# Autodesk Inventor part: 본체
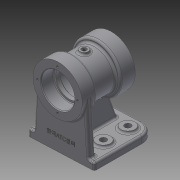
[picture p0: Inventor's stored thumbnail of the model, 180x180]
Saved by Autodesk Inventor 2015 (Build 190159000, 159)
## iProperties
Created: 2024-02
Part Number: 본체
Material: 알루미늄 6061
Document SubType Name: Modeling
Designer: 10420
Density: 2.7 g/cm^3
Appearance: 기본값
Mass: 719.296 g
Surface Area: 648.301 cm^2
Volume: 266.406 cm^3
Author: 10420
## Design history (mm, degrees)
sketch "스케치1"
  geometry: L1 (0, 0)-(0, -78); L2 (0, 0)-(35, 0); L3 (35, 0)-(35, -22); L4 (35, -22)-(28.5, -22); L5 (28.5, -22)-(28.5, -56); L6 (28.5, -56)-(35, -56); L7 (35, -56)-(35, -78); L8 (35, -78)-(0, -78)
  constraints: 16 end point, 5 perpendicular, 2 point on line, 1 horizontal, 1 vertical
  dimensions: "d0" = 78 distance of L1.start L1.end; "d1" = 70 diameter of L3 L1; "d2" = 57 diameter of L5 L1; "d3" = 22 distance between parallel lines of L2 L4; "d4" = 22 distance between parallel lines of L8 L6
revolve "회전1" sketch "스케치1" stored, may be unused: angle "d5" = 90 deg
sketch "스케치3"
  geometry: C1 r 35 at (0, 0) reference; C2 r 23.5 at (0, 0)
  constraints: 1 centre point, 1 coincident
  dimensions: "d18" = 47 diameter of C2
extrude "돌출1" cut sketch "스케치3" distance "d19" = 18; taper "d20" = 0 deg
sketch "스케치4"
  geometry: C1 r 35 at (0, 0) reference; C2 r 23.5 at (0, 0)
  constraints: 1 centre point, 1 coincident
  dimensions: "d21" = 47 diameter of C2
extrude "돌출2" cut sketch "스케치4" distance "d22" = 18; taper "d23" = 0 deg
sketch "스케치5"
  geometry: C1 r 23.5 at (0, 0) reference; C2 r 20 at (0, 0)
  constraints: 1 centre point, 1 coincident
  dimensions: "d24" = 40 diameter of C2
extrude "돌출3" cut sketch "스케치5" distance "d25" = 6; taper "d26" = 0 deg
sketch "스케치6"
  geometry: C1 r 20 at (0, 0) reference; C2 r 23.5 at (0, 0)
  constraints: 1 centre point, 1 coincident
  dimensions: "d27" = 47 diameter of C2
extrude "돌출4" cut sketch "스케치6" distance "d28" = 30; taper "d29" = 0 deg
sketch "스케치7"
  geometry: C1 r 23.5 at (0, 0) reference; C2 r 20 at (0, 0)
  constraints: 1 centre point, 1 coincident
  dimensions: "d30" = 40 diameter of C2
extrude "돌출5" cut sketch "스케치7" distance "d31" = 6; taper "d32" = 0 deg
sketch "스케치8"
  geometry: L1 (23.5, -18)-(23.5, 0) reference; L2 (23.5, 0)-(35, 0) reference; L3 (35, 0)-(35, -22) reference; L4 (35, -22)-(28.5, -22) reference; L5 (28.5, -22)-(28.5, -56) reference; L6 (28.5, -56)-(35, -56) reference; L7 (35, -56)-(35, -78) reference; L8 (35, -78)-(23.5, -78) reference; L9 (23.5, -78)-(23.5, -60) reference; L10 (23.5, -60)-(20, -60) reference; L11 (20, -60)-(20, -54) reference; L12 (20, -54)-(23.5, -54) reference; L13 (23.5, -54)-(23.5, -24) reference; L14 (23.5, -24)-(20, -24) reference; L15 (20, -24)-(20, -18) reference; L16 (20, -18)-(23.5, -18) reference; L17 (-23.5, 0)-(-23.5, -18) reference; L18 (-23.5, -18)-(-20, -18) reference; L19 (-20, -18)-(-20, -24) reference; L20 (-20, -24)-(-23.5, -24) reference; L21 (-23.5, -24)-(-23.5, -54) reference; L22 (-23.5, -54)-(-20, -54) reference; L23 (-20, -54)-(-20, -60) reference; L24 (-20, -60)-(-23.5, -60) reference; L25 (-23.5, -60)-(-23.5, -78) reference; L26 (-23.5, -78)-(-35, -78) reference; L27 (-35, -78)-(-35, -56) reference; L28 (-35, -56)-(-28.5, -56) reference; L29 (-28.5, -56)-(-28.5, -22) reference; L30 (-28.5, -22)-(-35, -22) reference; L31 (-35, -22)-(-35, 0) reference; L32 (-35, 0)-(-23.5, 0) reference; L33 (-70, -5)-(-80, -5); L34 (-80, -5)-(-80, -95); L35 (-80, -95)-(-70, -95); L36 (-70, -95)-(-70, -5); L37 (-35, 0)-(35, 0) reference; L38 (0, 0)-(0, 44)
  constraints: 10 end point, 2 parallel, 1 horizontal, 1 perpendicular, 1 vertical
  dimensions: "d33" = 5 distance between parallel lines of L33 L37; "d34" = 90 distance of L33.end L34.end; "d35" = 80 distance between parallel lines of L34 L38; "d36" = 10 distance of L34.end L35.end
extrude "돌출6" join sketch "스케치8" stored distance "d37" = 94; taper "d38" = 0 deg
node "작업 평면1"
sketch "스케치9"
  geometry: L1 (-47, -80)-(-47, -70) reference; L2 (-47, -70)-(47, -70) reference; L3 (47, -70)-(47, -80) reference; L4 (47, -80)-(-47, -80) reference; L5 (-34.945, 1.969)-(-39, -70); L6 (-47, -70)-(47, -70) reference; L7 (39, -70)-(34.945, 1.969); L8 (39, -70)-(-39, -70); C1 r 23.5 at (0, 0) reference; A1 r 35 centre (0, 0) between (-34.945, 1.969) and (34.945, 1.969) reference; 1 further point
  constraints: 6 end point, 2 point on circle, 2 point on line, 2 tangent, 1 collinear
  dimensions: "d41" = 8 distance from line of L1 L5.end; "d42" = 8 distance from line of L3 L7.start
extrude "돌출7" join sketch "스케치9" distance "d43" = 10; taper "d44" = 0 deg
sketch "스케치10"
  geometry: L1 (23.5, -18)-(23.5, 0) reference; L2 (23.5, 0)-(35, 0) reference; L3 (35, 0)-(35, -22) reference; L4 (35, -22)-(28.5, -22) reference; L5 (28.5, -22)-(28.5, -56) reference; L6 (28.5, -56)-(35, -56) reference; L7 (35, -56)-(35, -78) reference; L8 (35, -78)-(23.5, -78) reference; L9 (23.5, -78)-(23.5, -60) reference; L10 (23.5, -60)-(20, -60) reference; L11 (20, -60)-(20, -54) reference; L12 (20, -54)-(23.5, -54) reference; L13 (23.5, -54)-(23.5, -24) reference; L14 (23.5, -24)-(20, -24) reference; L15 (20, -24)-(20, -18) reference; L16 (20, -18)-(23.5, -18) reference; L17 (-23.5, 0)-(-23.5, -18) reference; L18 (-23.5, -18)-(-20, -18) reference; L19 (-20, -18)-(-20, -24) reference; L20 (-20, -24)-(-23.5, -24) reference; L21 (-23.5, -24)-(-23.5, -54) reference; L22 (-23.5, -54)-(-20, -54) reference; L23 (-20, -54)-(-20, -60) reference; L24 (-20, -60)-(-23.5, -60) reference; L25 (-23.5, -60)-(-23.5, -78) reference; L26 (-23.5, -78)-(-35, -78) reference; L27 (-35, -78)-(-35, -56) reference; L28 (-35, -56)-(-28.5, -56) reference; L29 (-28.5, -56)-(-28.5, -22) reference; L30 (-28.5, -22)-(-35, -22) reference; L31 (-35, -22)-(-35, -15) reference; L32 (-35, -15)-(-70, -15) reference; L33 (-70, -15)-(-70, -95) reference; L34 (-70, -95)-(-80, -95) reference; L35 (-80, -95)-(-80, -5) reference; L36 (-80, -5)-(-35, -5) reference; L37 (-35, -5)-(-35, 0) reference; L38 (-35, 0)-(-23.5, 0) reference; L39 (-35, -70.261)-(-70, -83); L40 (-70, -5)-(-70, -95) reference; 1 further point
  constraints: 2 end point, 2 point on line
  dimensions: "d45" = 12 distance from line of L34 L39.end; "d46" = 70 deg angle of L40 L39
feature "리브1" sketch "스케치10" dims "d47" = 1, "d48" = 10, "d49" = 0, "d50" = 0, "d51" = 1, "d52" = 1
fillet "모깎기1" dims "d53" = 20
sketch "스케치12"
  geometry: C1 r 10 at (20, 70); A1 r 20 centre (20, 70) between (20, 90) and (0, 70) reference; 1 further point
  constraints: 1 centre point, 1 coincident
  dimensions: "d54" = 20 diameter of C1
extrude "돌출8" join sketch "스케치12" distance "d55" = 3; taper "d56" = 0 deg
sketch "스케치13"
  geometry: C1 r 10 at (0, 0) reference; C2 r 4.5 at (0, 0); 1 further point
  constraints: 1 centre point, 1 coincident
  dimensions: "d57" = 9 diameter of C2
extrude "돌출9" cut sketch "스케치13" distance "d58" = 13; taper "d59" = 0 deg
sketch "스케치16" dims "d66" = 57
  geometry: C1 r 35 at (0, 0) reference; C2 r 23.5 at (0, 0) reference; C3 r 23.5 at (0, 0) reference; 2 further points
  constraints: 3 coincident, 2 vertical alignment, 2 other
hole "구멍1" sketch "스케치16" at (0, 28.5) diameter "d67" = 3.242; stored, may be unused: countersink angle "d71" = 90 deg, drill point angle "d73" = 118 deg; dims "d68" = 8, "d69" = 4, "d70" = 2, "d72" = 10
node "작업 평면2"
node "작업 평면3"
sketch "스케치17"
  geometry: C1 r 6 at (0, -39); 1 further point
  constraints: 1 centre point, 1 vertical alignment
  dimensions: "d79" = 12 diameter of C1; "d80" = 39 distance of point (0, 0) C1.centre
extrude "돌출10" join sketch "스케치17" stored distance "d81" = 13; taper "d82" = 0 deg
sketch "스케치19"
  geometry: C1 r 6 at (0, 0) reference; 2 further points
  constraints: 1 coincident
hole "구멍2" sketch "스케치19" at (0, 0) diameter "d83" = 5.188; stored, may be unused: countersink angle "d87" = 90 deg, drill point angle "d89" = 118 deg; dims "d84" = 12, "d85" = 7, "d86" = 2, "d88" = 19.25
fillet "모깎기2" dims "d90" = 3
fillet "모깎기3" dims "d91" = 3, "d92" = 1
fillet "모깎기4" dims "d93" = 3
fillet "모깎기5" dims "d94" = 3
fillet "모깎기6" dims "d95" = 3
chamfer "모따기1" distance "d96" = 1; stored, may be unused: second distance "d97" = 2, angle "d98" = 45 deg
chamfer "모따기2" distance "d99" = 1; stored, may be unused: second distance "d100" = 2, angle "d101" = 45 deg
sketch "스케치20"
  geometry: L1 (0, 0)-(88, 0) reference; 2 further points
  constraints: 1 midpoint, 1 vertical alignment, 1 other
  dimensions: "d102" = 20 distance from line of L1 point (44, 20)
feature "엠보싱1" sketch "스케치20" dims "d21" = 47, "d103" = 0.5, "d104" = 0
fillet "모깎기7" dims "d105" = 3
node "솔리드1"
pattern_linear "직사각형 패턴1" dims "d62" = 54, "d65" = 36
pattern_circular "원형 패턴1" dims angle "d75" = 360 deg
mirror "대칭1"
node "절단 모서리 투영2"
node "절단 모서리 투영3"
node "절단 모서리 투영4"
other parameters: "d39" = -5, "d77" = -39, "d78" = 31.5
